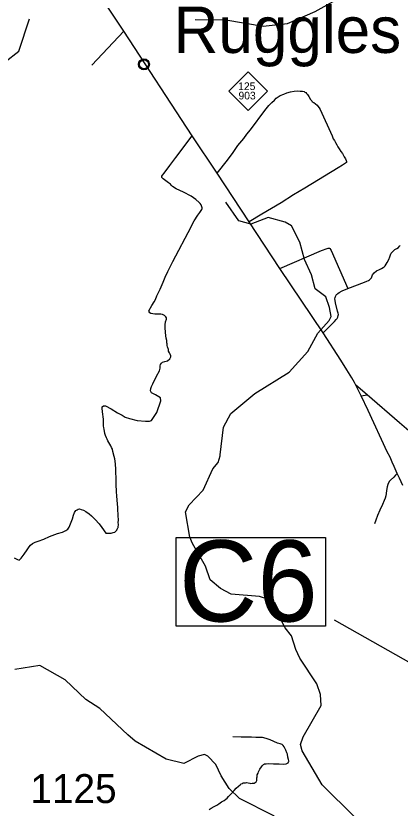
# Model space of a CAD drawing. Extents: x 2290615 to 2522933, y 819489 to 1012715.
# Drawn here: x 2413834 to 2420461, y 906842 to 920524 of the extents above; entities that cross this region are included whole.
import ezdxf

# ---------------------------------------------------------------- set-up
doc = ezdxf.new("R2010")
doc.units = 0
for name, color, linetype in [('Exist Civil Demographics City Label', 7, 'Continuous'), ('Exist Civil Demographics Community CELL', 7, 'Continuous'), ('Exist Hydrographic Misc Water Feature', 7, 'Continuous'), ('Exist Road Non-System Type 51', 7, 'Continuous'), ('Exist Road Primary NC Attributed', 7, 'Continuous'), ('Exist Road Primary NC Shield CELL', 7, 'Continuous'), ('Exist Road Primary NC Shield Number Label', 7, 'Continuous'), ('Exist Road Primary NC Structure Culvert Number Label', 7, 'Continuous'), ('Exist Road Secondary Type 51 Attributed', 7, 'Continuous'), ('Exist Road Secondary Type 51 Number Label', 7, 'Continuous')]:
    doc.layers.add(name, color=color, linetype=linetype)

msp = doc.modelspace()

# ---------------------------------------------------------------- linework, layer by layer
at = {"layer": 'Exist Civil Demographics Community CELL'}
msp.add_lwpolyline([(2415965, 919700), (2415966, 919705), (2415968, 919712), (2415971, 919719), (2415974, 919725), (2415977, 919731), (2415981, 919736), (2415985, 919740), (2415989, 919745), (2415995, 919749), (2416000, 919753), (2416005, 919756), (2416010, 919758), (2416016, 919760), (2416021, 919762), (2416026, 919763), (2416031, 919764), (2416035, 919765), (2416041, 919765), (2416046, 919765), (2416051, 919765), (2416056, 919764), (2416061, 919763), (2416066, 919762), (2416071, 919760), (2416078, 919757), (2416084, 919753), (2416089, 919750), (2416094, 919746), (2416098, 919743), (2416102, 919738), (2416106, 919734), (2416109, 919729), (2416112, 919724), (2416114, 919719), (2416116, 919714), (2416118, 919709), (2416119, 919704), (2416120, 919698), (2416121, 919693), (2416121, 919687), (2416121, 919682), (2416120, 919676), (2416119, 919670), (2416118, 919664), (2416116, 919658), (2416114, 919653), (2416110, 919647), (2416107, 919642), (2416104, 919637), (2416100, 919633), (2416094, 919628), (2416089, 919624), (2416084, 919620), (2416080, 919618), (2416073, 919614), (2416066, 919612), (2416060, 919610), (2416053, 919609), (2416049, 919608), (2416044, 919608), (2416039, 919608), (2416035, 919609), (2416029, 919609), (2416023, 919611), (2416018, 919612), (2416013, 919614), (2416009, 919616), (2416005, 919618), (2415998, 919622), (2415992, 919626), (2415987, 919631), (2415983, 919636), (2415980, 919640), (2415977, 919644), (2415973, 919651), (2415971, 919654), (2415969, 919659), (2415967, 919667), (2415965, 919674), (2415964, 919679), (2415964, 919685), (2415964, 919690), (2415965, 919696)], close=True, dxfattribs=at)
for centre, radius in [((2416043, 919687), 94.3), ((2416043, 919688), 76.7)]:
    msp.add_circle(centre, radius, dxfattribs=at)
at = {"layer": 'Exist Hydrographic Misc Water Feature'}
for points in [[(2416929, 920464), (2417454, 920456), (2418097, 920348), (2418521, 920395), (2418993, 920601), (2419770, 921037), (2419976, 921209), (2420273, 921379), (2420980, 921506), (2421715, 921973), (2421806, 921977), (2421898, 921935)], [(2413648, 919732), (2413887, 919912), (2414071, 920471)], [(2417355, 912927), (2417357, 912945), (2417414, 913422), (2417544, 913657), (2417956, 914003), (2418550, 914372), (2418870, 914726), (2419040, 915045), (2419237, 915263), (2419270, 915330), (2419242, 915490), (2419181, 915671), (2418996, 915811), (2418934, 916052), (2418814, 916316), (2418734, 916615), (2418588, 916898), (2418479, 916962), (2418187, 917042), (2417888, 916928), (2417679, 916982), (2417458, 917304)], [(2419677, 906687), (2419119, 907245), (2418769, 907831), (2418742, 907942), (2418790, 908075), (2419099, 908613), (2419088, 908803), (2419027, 908988), (2418729, 909432), (2418660, 909580), (2418590, 909820), (2418479, 909953), (2418428, 910053), (2418366, 910267), (2418306, 910383), (2418197, 910447), (2418038, 910497), (2417546, 910539), (2417361, 910636), (2417184, 910783), (2417106, 911023), (2416883, 911414), (2416832, 911521), (2416759, 911961), (2416824, 912078), (2417062, 912331), (2417231, 912703), (2417321, 912811), (2417355, 912927)], [(2419837, 906007), (2419545, 906018), (2419376, 906159), (2418681, 906400), (2418555, 906463), (2418285, 906708), (2417689, 907009), (2417511, 907182), (2417375, 907397), (2417281, 907593), (2417145, 907742), (2417086, 907766), (2416978, 907738), (2416730, 907610), (2416429, 907689), (2415891, 907999), (2415765, 908105), (2415283, 908565), (2415039, 908719), (2414685, 909056), (2414248, 909307), (2413816, 909234)]]:
    msp.add_lwpolyline(points, dxfattribs=at)
at = {"layer": 'Exist Road Non-System Type 51'}
for p, q in [((2415144, 919672), (2415694, 920258)), ((2419787, 913964), (2419894, 913979))]:
    msp.add_line(p, q, dxfattribs=at)
for points in [[(2417304, 917807), (2417485, 918034), (2417581, 918164), (2417665, 918285), (2417766, 918408), (2417819, 918479), (2417879, 918556), (2418127, 918888), (2418199, 918975), (2418249, 919027), (2418296, 919070), (2418325, 919102), (2418357, 919125), (2418395, 919150), (2418456, 919174), (2418508, 919197), (2418572, 919214), (2418636, 919225), (2418697, 919230), (2418736, 919225), (2418780, 919221), (2418804, 919216), (2418820, 919206), (2418832, 919198), (2418848, 919186), (2418861, 919168), (2418887, 919129), (2418916, 919081), (2418922, 919075), (2418936, 919055), (2418946, 919042), (2418974, 919026), (2419031, 918981), (2419043, 918963), (2419064, 918937), (2419082, 918908), (2419287, 918453), (2419309, 918403), (2419330, 918369), (2419346, 918339), (2419371, 918295), (2419388, 918261), (2419411, 918229), (2419440, 918182), (2419465, 918145), (2419478, 918122), (2419495, 918090), (2419519, 918053), (2419532, 918024), (2419539, 918009), (2419537, 917992), (2419470, 917947), (2419391, 917898), (2418820, 917549), (2418622, 917431), (2418410, 917295), (2418074, 917101), (2417856, 916968)], [(2416353, 917758), (2416362, 917771), (2416391, 917810), (2416490, 917941), (2416595, 918080), (2416876, 918451)], [(2415343, 913520), (2415343, 913559), (2415328, 913686), (2415324, 913749), (2415324, 913774), (2415343, 913792), (2415378, 913792), (2415476, 913740), (2415588, 913671), (2415666, 913626), (2415717, 913595), (2415793, 913568), (2415927, 913538), (2416070, 913526), (2416140, 913524), (2416174, 913536), (2416265, 913677), (2416337, 913877), (2416328, 913930), (2416244, 913977), (2416175, 914016), (2416158, 914046), (2416162, 914089), (2416175, 914124), (2416199, 914171), (2416262, 914303), (2416313, 914392), (2416321, 914438), (2416323, 914480), (2416330, 914505), (2416343, 914525), (2416363, 914541), (2416401, 914555), (2416450, 914564), (2416491, 914601), (2416507, 914634), (2416504, 914655), (2416495, 914680), (2416483, 914707), (2416469, 914732), (2416465, 914764), (2416448, 914808), (2416444, 914832), (2416441, 914858), (2416438, 914875), (2416435, 914916), (2416426, 914956), (2416421, 915001), (2416408, 915132), (2416408, 915186), (2416413, 915242), (2416432, 915286), (2416433, 915309), (2416421, 915327), (2416399, 915349), (2416363, 915369), (2416332, 915374), (2416280, 915370), (2416228, 915372), (2416164, 915386), (2416142, 915397), (2416131, 915411), (2416130, 915429), (2416178, 915521), (2416221, 915583), (2416240, 915628), (2416266, 915687), (2416322, 915806), (2416374, 915926), (2416409, 916011), (2416455, 916110), (2416500, 916200), (2416539, 916283), (2416595, 916382), (2416808, 916783), (2416911, 916982), (2416975, 917082), (2417004, 917130), (2417031, 917163), (2417040, 917181), (2417045, 917197), (2417045, 917211), (2417040, 917228), (2417030, 917262), (2417013, 917286), (2416995, 917303), (2416938, 917353), (2416860, 917409), (2416728, 917477), (2416599, 917538), (2416536, 917576), (2416517, 917596), (2416499, 917618), (2416465, 917643), (2416399, 917690), (2416374, 917708), (2416361, 917722), (2416354, 917733), (2416349, 917744), (2416353, 917758)], [(2418386, 916163), (2419105, 916474), (2419205, 916506), (2419219, 916510), (2419231, 916514), (2419241, 916512), (2419255, 916504), (2419261, 916492), (2419272, 916470), (2419561, 915816)], [(2419561, 915816), (2419844, 915927), (2419889, 915941), (2419913, 915951), (2419931, 915968), (2419966, 916002), (2419987, 916049), (2420014, 916088), (2420053, 916118), (2420106, 916141), (2420140, 916161), (2420168, 916176), (2420184, 916190), (2420203, 916206), (2420223, 916236), (2420239, 916267), (2420266, 916315), (2420281, 916361), (2420295, 916397), (2420308, 916428), (2420336, 916456), (2420348, 916466), (2420371, 916487), (2420405, 916507), (2420433, 916525), (2420451, 916544), (2420462, 916560)], [(2419131, 915048), (2419330, 915243), (2419359, 915280), (2419373, 915300), (2419384, 915322), (2419395, 915347), (2419398, 915366), (2419393, 915388), (2419383, 915422), (2419345, 915568), (2419338, 915607), (2419334, 915635), (2419341, 915660), (2419347, 915676), (2419353, 915690), (2419363, 915710), (2419375, 915720), (2419388, 915728), (2419409, 915746), (2419459, 915773), (2419561, 915816)], [(2413805, 911167), (2413865, 911133), (2413892, 911126), (2413926, 911160), (2413977, 911227), (2414028, 911303), (2414062, 911357), (2414089, 911383), (2414122, 911412), (2414169, 911433), (2414221, 911455), (2414315, 911489), (2414415, 911531), (2414551, 911582), (2414636, 911609), (2414697, 911634), (2414728, 911658), (2414753, 911694), (2414777, 911750), (2414811, 911837), (2414829, 911902), (2414846, 911947), (2414871, 911980), (2414889, 911996), (2414909, 912005), (2414929, 912010), (2414960, 912001), (2414998, 911987), (2415039, 911963), (2415099, 911925), (2415141, 911887), (2415200, 911824), (2415269, 911750), (2415314, 911688), (2415383, 911591), (2415416, 911589), (2415437, 911588), (2415458, 911589), (2415475, 911593), (2415493, 911596), (2415514, 911601), (2415534, 911607), (2415540, 911610), (2415546, 911615), (2415556, 911624), (2415567, 911635), (2415574, 911645), (2415583, 911660), (2415594, 911681), (2415598, 911691), (2415601, 911704), (2415602, 911731), (2415603, 911746), (2415601, 911771), (2415601, 911791), (2415602, 911806), (2415602, 911842), (2415600, 911868), (2415598, 911908), (2415597, 911930), (2415595, 911977), (2415590, 912035), (2415587, 912095), (2415582, 912158), (2415573, 912234), (2415570, 912304), (2415570, 912336), (2415564, 912402), (2415566, 912476), (2415566, 912549), (2415559, 912634), (2415556, 912694), (2415550, 912784), (2415544, 912836), (2415540, 912876), (2415532, 912912), (2415508, 913002), (2415498, 913039), (2415486, 913072), (2415473, 913098), (2415453, 913129), (2415440, 913155), (2415420, 913187), (2415407, 913211), (2415398, 913237), (2415380, 913275), (2415370, 913312), (2415361, 913352), (2415356, 913379), (2415350, 913416), (2415346, 913438), (2415345, 913459), (2415345, 913493), (2415343, 913520)], [(2420412, 912623), (2420380, 912590), (2420351, 912560), (2420295, 912508), (2420273, 912481), (2420250, 912432), (2420235, 912389), (2420224, 912328), (2420218, 912274), (2420213, 912234), (2420205, 912196), (2420186, 912152), (2420157, 912085), (2420113, 911988), (2420073, 911893), (2420041, 911813), (2420020, 911754)], [(2417166, 906819), (2417203, 906842), (2417253, 906868), (2417298, 906893), (2417332, 906916), (2417383, 906953), (2417424, 906976), (2417453, 906994), (2417477, 907014), (2417504, 907044), (2417533, 907076), (2417600, 907147), (2417636, 907188), (2417675, 907223), (2417704, 907246), (2417721, 907259), (2417741, 907270), (2417755, 907277), (2417768, 907278), (2417792, 907280), (2417810, 907282), (2417842, 907280), (2417867, 907275), (2417888, 907270), (2417909, 907272), (2417927, 907274), (2417941, 907275), (2417963, 907282), (2417980, 907297), (2417991, 907321), (2417991, 907345), (2417992, 907367), (2417993, 907383), (2417993, 907399), (2417998, 907418), (2418010, 907446), (2418020, 907471), (2418029, 907493), (2418043, 907513), (2418070, 907555), (2418090, 907577), (2418106, 907593), (2418115, 907604), (2418122, 907605), (2418133, 907608), (2418148, 907609), (2418194, 907611), (2418279, 907609), (2418377, 907605), (2418448, 907604), (2418495, 907606), (2418509, 907611), (2418520, 907619), (2418528, 907626), (2418538, 907641), (2418541, 907647), (2418541, 907660), (2418537, 907681), (2418526, 907724), (2418516, 907773), (2418508, 907798), (2418489, 907842), (2418473, 907876), (2418461, 907902), (2418445, 907926), (2418428, 907942), (2418393, 907952), (2418348, 907966), (2418284, 907991), (2418222, 908019), (2418169, 908041), (2418113, 908058), (2418090, 908060), (2418041, 908061), (2417970, 908064), (2417896, 908065), (2417719, 908068), (2417576, 908073)]]:
    msp.add_lwpolyline(points, dxfattribs=at)
at = {"layer": 'Exist Road Primary NC Attributed'}
for points in [[(2419697, 914147), (2419675, 914195), (2419628, 914272), (2419544, 914411), (2419439, 914577), (2419131, 915048), (2418386, 916163), (2417856, 916968), (2417304, 917807), (2416876, 918451), (2415694, 920258), (2414865, 921523), (2414651, 921851), (2414622, 921898), (2413481, 923576)], [(2420505, 912415), (2420453, 912542), (2420412, 912623), (2420359, 912741), (2420326, 912818), (2420289, 912903), (2420240, 912994), (2419912, 913710), (2419787, 913964), (2419697, 914147)]]:
    msp.add_lwpolyline(points, dxfattribs=at)
at = {"layer": 'Exist Road Primary NC Shield CELL'}
msp.add_lwpolyline([(2417509, 919222), (2417842, 919555), (2418175, 919222), (2417842, 918889)], close=True, dxfattribs=at)
at = {"layer": 'Exist Road Primary NC Structure Culvert Number Label'}
msp.add_line((2423196, 907889), (2419332, 910089), dxfattribs=at)
msp.add_lwpolyline([(2416596, 911516), (2419173, 911516), (2419173, 909987), (2416596, 909987)], close=True, dxfattribs=at)
at = {"layer": 'Exist Road Secondary Type 51 Attributed'}
msp.add_lwpolyline([(2420611, 913358), (2420452, 913498), (2419894, 913979), (2419697, 914147)], dxfattribs=at)

# ---------------------------------------------------------------- texts
at = {"layer": 'Exist Civil Demographics City Label'}
msp.add_text('Ruggles', height=800, rotation=360, dxfattribs=at).set_placement((2416554, 919884))
at = {"layer": 'Exist Road Primary NC Shield Number Label'}
for s, p in [('125', (2417669, 919243)), ('903', (2417674, 919081))]:
    msp.add_text(s, height=132.5, dxfattribs=at).set_placement(p)
at = {"layer": 'Exist Road Primary NC Structure Culvert Number Label'}
msp.add_text('C6', height=1400, dxfattribs=at).set_placement((2416647, 910066))
at = {"layer": 'Exist Road Secondary Type 51 Number Label'}
msp.add_text('1125', height=500, rotation=360, dxfattribs=at).set_placement((2414084, 906929))

doc.saveas('drawing.dxf')
